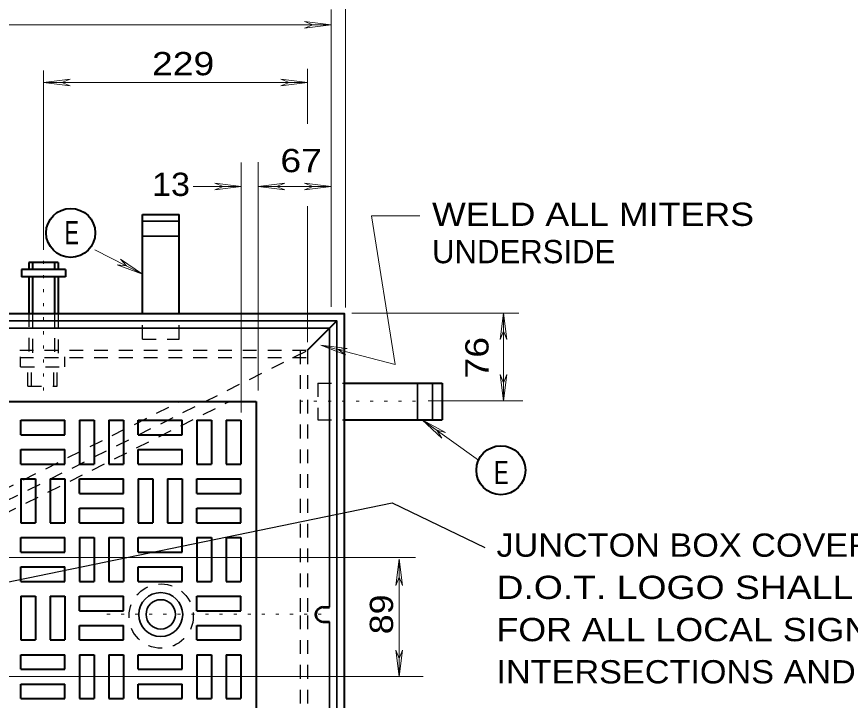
# Model space of a CAD drawing. Extents: x 312583 to 312854, y 144419 to 144597.
# Drawn here: x 312714.2 to 312741.44, y 144549.93 to 144572.27 of the extents above; entities that cross this region are included whole.
import ezdxf

# ---------------------------------------------------------------- set-up
doc = ezdxf.new("R2010")
doc.units = 0
doc.header["$LTSCALE"] = 0.3
doc.linetypes.add('DOTTED', pattern=[1.5, 0.3, -1.2])
doc.linetypes.add('SHORT_DASHED', pattern=[2.7, 1.5, -1.2])
doc.layers.add('1', color=7, linetype='Continuous', lineweight=40)
doc.layers.add('2', color=7, linetype='Continuous', lineweight=13)

msp = doc.modelspace()

# ---------------------------------------------------------------- linework, layer by layer
at = {"layer": '1'}
for p, q in [((312718.3075, 144565.8076), (312719.5112, 144565.8076)), ((312718.3075, 144562.5876), (312718.3075, 144565.8076)), ((312719.5112, 144562.5799), (312719.5112, 144565.8076)), ((312715.5552, 144564.2436), (312714.5969, 144564.2436)), ((312714.5969, 144564.2436), (312714.5969, 144564.0059)), ((312714.7195, 144564.2436), (312714.7195, 144564.0059)), ((312715.4325, 144564.2436), (312715.4325, 144564.0059)), ((312715.5552, 144564.2436), (312715.5552, 144564.0059)), ((312715.7929, 144564.0059), (312714.3592, 144564.0059)), ((312714.3592, 144564.0059), (312714.3592, 144563.7683)), ((312715.7929, 144564.0059), (312715.7929, 144563.7683)), ((312715.7929, 144563.7683), (312714.3592, 144563.7683)), ((312714.5969, 144563.7683), (312714.5969, 144562.5876)), ((312714.7195, 144563.7683), (312714.7195, 144562.5646)), ((312715.4325, 144563.7683), (312715.4325, 144562.5723)), ((312715.5552, 144563.7683), (312715.5552, 144562.5799)), ((312723.7049, 144561.3686), (312724.6632, 144562.3269)), ((312724.9009, 144560.2953), (312728.1055, 144560.2953)), ((312728.1055, 144560.2953), (312728.1055, 144559.0916)), ((312690.8762, 144559.6973), (312722.0259, 144559.6973)), ((312722.0259, 144559.6973), (312722.0259, 144545.7976)), ((312714.3362, 144559.0839), (312715.7699, 144559.0839)), ((312714.3362, 144558.6086), (312714.3362, 144559.0839)), ((312715.7699, 144558.6086), (312715.7699, 144559.0839)), ((312716.2529, 144559.0839), (312716.2529, 144557.6503)), ((312716.2529, 144559.0839), (312716.7282, 144559.0839)), ((312716.7282, 144559.0839), (312716.7282, 144557.6503)), ((312717.2112, 144559.0839), (312717.2112, 144557.6503)), ((312717.2112, 144559.0839), (312717.6865, 144559.0839)), ((312717.6865, 144559.0839), (312717.6865, 144557.6503)), ((312718.1695, 144559.0839), (312719.6032, 144559.0839)), ((312718.1695, 144558.6086), (312718.1695, 144559.0839)), ((312719.6032, 144558.6086), (312719.6032, 144559.0839)), ((312720.0862, 144559.0839), (312720.0862, 144557.6503)), ((312720.0862, 144559.0839), (312720.5615, 144559.0839)), ((312720.5615, 144559.0839), (312720.5615, 144557.6503)), ((312721.0445, 144559.0839), (312721.0445, 144557.6503)), ((312721.0445, 144559.0839), (312721.5199, 144559.0839)), ((312721.5199, 144559.0839), (312721.5199, 144557.6503)), ((312724.9392, 144559.0916), (312728.1055, 144559.0916)), ((312714.3362, 144558.6086), (312715.7699, 144558.6086)), ((312718.1695, 144558.6086), (312719.6032, 144558.6086)), ((312714.3362, 144558.1256), (312715.7699, 144558.1256)), ((312714.3362, 144557.6503), (312714.3362, 144558.1256)), ((312715.7699, 144557.6503), (312715.7699, 144558.1256)), ((312718.1695, 144558.1256), (312719.6032, 144558.1256)), ((312718.1695, 144557.6503), (312718.1695, 144558.1256)), ((312719.6032, 144557.6503), (312719.6032, 144558.1256)), ((312714.3362, 144557.6503), (312715.7699, 144557.6503)), ((312716.2529, 144557.6503), (312716.7282, 144557.6503)), ((312717.2112, 144557.6503), (312717.6865, 144557.6503)), ((312718.1695, 144557.6503), (312719.6032, 144557.6503)), ((312720.0862, 144557.6503), (312720.5615, 144557.6503)), ((312721.0445, 144557.6503), (312721.5199, 144557.6503)), ((312714.3362, 144557.1673), (312714.3362, 144555.7336)), ((312714.3362, 144557.1673), (312714.8115, 144557.1673)), ((312714.8115, 144557.1673), (312714.8115, 144555.7336)), ((312715.2945, 144557.1673), (312715.2945, 144555.7336)), ((312715.2945, 144557.1673), (312715.7699, 144557.1673)), ((312715.7699, 144557.1673), (312715.7699, 144555.7336)), ((312716.2529, 144557.1673), (312717.6865, 144557.1673)), ((312716.2529, 144556.6919), (312716.2529, 144557.1673)), ((312717.6865, 144556.6919), (312717.6865, 144557.1673)), ((312718.1695, 144557.1673), (312718.1695, 144555.7336)), ((312718.1695, 144557.1673), (312718.6449, 144557.1673)), ((312718.6449, 144557.1673), (312718.6449, 144555.7336)), ((312719.1279, 144557.1673), (312719.1279, 144555.7336)), ((312719.1279, 144557.1673), (312719.6032, 144557.1673)), ((312719.6032, 144557.1673), (312719.6032, 144555.7336)), ((312720.0862, 144557.1673), (312721.5199, 144557.1673)), ((312720.0862, 144556.6919), (312720.0862, 144557.1673)), ((312721.5199, 144556.6919), (312721.5199, 144557.1673)), ((312716.2529, 144556.6919), (312717.6865, 144556.6919)), ((312720.0862, 144556.6919), (312721.5199, 144556.6919)), ((312716.2529, 144556.2089), (312717.6865, 144556.2089)), ((312716.2529, 144555.7336), (312716.2529, 144556.2089)), ((312717.6865, 144555.7336), (312717.6865, 144556.2089)), ((312720.0862, 144556.2089), (312721.5199, 144556.2089)), ((312720.0862, 144555.7336), (312720.0862, 144556.2089)), ((312721.5199, 144555.7336), (312721.5199, 144556.2089)), ((312714.3362, 144555.7336), (312714.8115, 144555.7336)), ((312715.2945, 144555.7336), (312715.7699, 144555.7336)), ((312716.2529, 144555.7336), (312717.6865, 144555.7336)), ((312718.1695, 144555.7336), (312718.6449, 144555.7336)), ((312719.1279, 144555.7336), (312719.6032, 144555.7336)), ((312720.0862, 144555.7336), (312721.5199, 144555.7336)), ((312714.3362, 144555.2506), (312715.7699, 144555.2506)), ((312714.3362, 144554.7753), (312714.3362, 144555.2506)), ((312715.7699, 144554.7753), (312715.7699, 144555.2506)), ((312716.2529, 144555.2506), (312716.2529, 144553.8169)), ((312716.2529, 144555.2506), (312716.7282, 144555.2506)), ((312716.7282, 144555.2506), (312716.7282, 144553.8169)), ((312717.2112, 144555.2506), (312717.2112, 144553.8169)), ((312717.2112, 144555.2506), (312717.6865, 144555.2506)), ((312717.6865, 144555.2506), (312717.6865, 144553.8169)), ((312718.1695, 144555.2506), (312719.6032, 144555.2506)), ((312718.1695, 144554.7753), (312718.1695, 144555.2506)), ((312719.6032, 144554.7753), (312719.6032, 144555.2506)), ((312720.0862, 144555.2506), (312720.0862, 144553.8169)), ((312720.0862, 144555.2506), (312720.5615, 144555.2506)), ((312720.5615, 144555.2506), (312720.5615, 144553.8169)), ((312721.0445, 144555.2506), (312721.0445, 144553.8169)), ((312721.0445, 144555.2506), (312721.5199, 144555.2506)), ((312721.5199, 144555.2506), (312721.5199, 144553.8169)), ((312714.3362, 144554.7753), (312715.7699, 144554.7753)), ((312718.1695, 144554.7753), (312719.6032, 144554.7753)), ((312714.3362, 144554.2923), (312715.7699, 144554.2923)), ((312714.3362, 144553.8169), (312714.3362, 144554.2923)), ((312715.7699, 144553.8169), (312715.7699, 144554.2923)), ((312718.1695, 144554.2923), (312719.6032, 144554.2923)), ((312718.1695, 144553.8169), (312718.1695, 144554.2923)), ((312719.6032, 144553.8169), (312719.6032, 144554.2923)), ((312714.3362, 144553.8169), (312715.7699, 144553.8169)), ((312716.2529, 144553.8169), (312716.7282, 144553.8169)), ((312717.2112, 144553.8169), (312717.6865, 144553.8169)), ((312718.1695, 144553.8169), (312719.6032, 144553.8169)), ((312720.0862, 144553.8169), (312720.5615, 144553.8169)), ((312721.0445, 144553.8169), (312721.5199, 144553.8169)), ((312714.3362, 144553.3339), (312714.3362, 144551.9003)), ((312714.3362, 144553.3339), (312714.8115, 144553.3339)), ((312714.8115, 144553.3339), (312714.8115, 144551.9003)), ((312715.2945, 144553.3339), (312715.2945, 144551.9003)), ((312715.2945, 144553.3339), (312715.7699, 144553.3339)), ((312715.7699, 144553.3339), (312715.7699, 144551.9003)), ((312716.2529, 144553.3339), (312717.6865, 144553.3339)), ((312716.2529, 144552.8586), (312716.2529, 144553.3339)), ((312717.6865, 144552.8586), (312717.6865, 144553.3339)), ((312720.0862, 144553.3339), (312721.5199, 144553.3339)), ((312720.0862, 144552.8586), (312720.0862, 144553.3339)), ((312721.5199, 144552.8586), (312721.5199, 144553.3339)), ((312716.2529, 144552.8586), (312717.6865, 144552.8586)), ((312720.0862, 144552.8586), (312721.5199, 144552.8586)), ((312716.2529, 144552.3756), (312717.6865, 144552.3756)), ((312716.2529, 144551.9003), (312716.2529, 144552.3756)), ((312717.6865, 144551.9003), (312717.6865, 144552.3756)), ((312720.0862, 144552.3756), (312721.5199, 144552.3756)), ((312720.0862, 144551.9003), (312720.0862, 144552.3756)), ((312721.5199, 144551.9003), (312721.5199, 144552.3756)), ((312714.3362, 144551.9003), (312714.8115, 144551.9003)), ((312715.2945, 144551.9003), (312715.7699, 144551.9003)), ((312716.2529, 144551.9003), (312717.6865, 144551.9003)), ((312720.0862, 144551.9003), (312721.5199, 144551.9003)), ((312714.3362, 144551.4173), (312715.7699, 144551.4173)), ((312714.3362, 144550.9419), (312714.3362, 144551.4173)), ((312715.7699, 144550.9419), (312715.7699, 144551.4173)), ((312716.2529, 144551.4173), (312716.2529, 144549.9836)), ((312716.2529, 144551.4173), (312716.7282, 144551.4173)), ((312716.7282, 144551.4173), (312716.7282, 144549.9836)), ((312717.2112, 144551.4173), (312717.2112, 144549.9836)), ((312717.2112, 144551.4173), (312717.6865, 144551.4173)), ((312717.6865, 144551.4173), (312717.6865, 144549.9836)), ((312718.1695, 144551.4173), (312719.6032, 144551.4173)), ((312718.1695, 144550.9419), (312718.1695, 144551.4173)), ((312719.6032, 144550.9419), (312719.6032, 144551.4173)), ((312720.0862, 144551.4173), (312720.0862, 144549.9836)), ((312720.0862, 144551.4173), (312720.5615, 144551.4173)), ((312720.5615, 144551.4173), (312720.5615, 144549.9836)), ((312721.0445, 144551.4173), (312721.0445, 144549.9836)), ((312721.0445, 144551.4173), (312721.5199, 144551.4173)), ((312721.5199, 144551.4173), (312721.5199, 144549.9836)), ((312714.3362, 144550.9419), (312715.7699, 144550.9419)), ((312718.1695, 144550.9419), (312719.6032, 144550.9419)), ((312714.3362, 144550.4589), (312715.7699, 144550.4589)), ((312714.3362, 144549.9836), (312714.3362, 144550.4589)), ((312715.7699, 144549.9836), (312715.7699, 144550.4589)), ((312718.1695, 144550.4589), (312719.6032, 144550.4589)), ((312718.1695, 144549.9836), (312718.1695, 144550.4589)), ((312719.6032, 144549.9836), (312719.6032, 144550.4589)), ((312714.3362, 144549.9836), (312715.7699, 144549.9836)), ((312716.2529, 144549.9836), (312716.7282, 144549.9836)), ((312717.2112, 144549.9836), (312717.6865, 144549.9836)), ((312718.1695, 144549.9836), (312719.6032, 144549.9836)), ((312720.0862, 144549.9836), (312720.5615, 144549.9836)), ((312721.0445, 144549.9836), (312721.5199, 144549.9836))]:
    msp.add_line(p, q, dxfattribs=at)
at = {"layer": '1', "lineweight": 35}
for p, q in [((312718.3075, 144565.5853), (312719.5112, 144565.5853)), ((312718.3075, 144565.1023), (312719.5112, 144565.1023)), ((312688.4842, 144562.0893), (312724.4179, 144562.0893)), ((312724.4179, 144562.0893), (312724.4179, 144552.9736)), ((312727.3005, 144560.2953), (312727.3005, 144559.0916)), ((312727.7835, 144560.2953), (312727.7835, 144559.0916)), ((312724.4179, 144552.4906), (312724.4179, 144543.4056))]:
    msp.add_line(p, q, dxfattribs=at)
at = {"layer": '1', "linetype": 'DOTTED', "lineweight": 13}
for p, q in [((312715.0799, 144564.7496), (312715.0799, 144559.9273)), ((312723.4519, 144559.7049), (312727.3312, 144559.7049)), ((312717.1499, 144552.7436), (312724.3489, 144552.7436))]:
    msp.add_line(p, q, dxfattribs=at)
at = {"layer": '1', "linetype": 'SHORT_DASHED', "lineweight": 25}
for p, q in [((312714.5969, 144562.5876), (312714.5969, 144561.1309)), ((312714.7195, 144562.5493), (312714.7195, 144561.1309)), ((312715.4325, 144562.5799), (312715.4325, 144561.1309)), ((312715.5552, 144562.5339), (312715.5552, 144561.1309)), ((312718.3075, 144561.7366), (312718.3075, 144562.5876)), ((312719.5112, 144561.7366), (312719.5112, 144562.5799)), ((312718.3075, 144561.7366), (312719.5112, 144561.7366)), ((312689.2049, 144544.1186), (312723.7049, 144561.3686)), ((312723.4595, 144561.3686), (312723.4595, 144552.7053)), ((312698.9109, 144561.1309), (312723.7049, 144561.1309)), ((312714.3285, 144560.8319), (312714.3285, 144561.1539)), ((312715.7699, 144560.8319), (312715.7699, 144561.1539)), ((312714.3285, 144560.8319), (312715.7699, 144560.8319)), ((312714.5662, 144560.1956), (312714.5662, 144560.8319)), ((312714.6889, 144560.1956), (312714.6889, 144560.8319)), ((312715.4095, 144560.1956), (312715.4095, 144560.8319)), ((312715.5245, 144560.1956), (312715.5245, 144560.8319)), ((312714.5662, 144560.1956), (312715.5245, 144560.1956)), ((312724.0345, 144560.2953), (312724.0345, 144559.0916)), ((312724.0345, 144560.2953), (312724.8855, 144560.2953)), ((312706.4549, 144553.1499), (312719.5419, 144559.6973)), ((312707.2522, 144552.7436), (312721.1519, 144559.6973)), ((312724.0345, 144559.0916), (312724.9239, 144559.0916)), ((312723.4595, 144552.7053), (312723.4595, 144544.1186))]:
    msp.add_line(p, q, dxfattribs=at)
at = {"layer": '1', "lineweight": 53}
for p, q in [((312724.2109, 144552.9736), (312724.4179, 144552.9736)), ((312724.2109, 144552.4906), (312724.4179, 144552.4906))]:
    msp.add_line(p, q, dxfattribs=at)
at = {"layer": '1'}
msp.add_lwpolyline([(312688.0012, 144562.5723), (312724.9009, 144562.5723), (312724.9009, 144542.9226)], dxfattribs=at)
at = {"layer": '1', "lineweight": 35}
msp.add_lwpolyline([(312688.2465, 144562.3269), (312724.6632, 144562.3269), (312724.6632, 144543.1603)], dxfattribs=at)
at = {"layer": '1', "linetype": 'SHORT_DASHED', "lineweight": 25}
for points in [[(312689.2049, 144561.3686), (312698.9109, 144561.3686), (312723.7049, 144561.3686)], [(312723.7049, 144561.3686), (312723.7049, 144552.7053), (312723.7049, 144544.1186)]]:
    msp.add_lwpolyline(points, dxfattribs=at)
at = {"layer": '1', "lineweight": 25}
msp.add_lwpolyline([(312711.6529, 144553.3339), (312726.4725, 144556.3853), (312729.4932, 144554.9286)], dxfattribs=at)
at = {"layer": '1', "linetype": 'SHORT_DASHED', "lineweight": 25}
msp.add_circle((312718.9213, 144552.6823), 1.0502, dxfattribs=at)
at = {"layer": '1', "lineweight": 35}
for centre, radius in [((312718.9048, 144552.7317), 0.7188), ((312718.9074, 144552.7379), 0.4792)]:
    msp.add_circle(centre, radius, dxfattribs=at)
at = {"layer": '1', "lineweight": 53}
msp.add_arc((312724.207, 144552.7331), 0.2396, 90, 270, dxfattribs=at)
at = {"layer": '2'}
for p, q in [((312724.9392, 144562.7639), (312724.9392, 144574.9386)), ((312724.4715, 144562.7946), (312724.4715, 144572.5083)), ((312688.4535, 144572.0099), (312724.4715, 144572.0099)), ((312723.6052, 144572.1173), (312723.8812, 144572.0099)), ((312724.4715, 144572.0099), (312723.6052, 144572.1173)), ((312723.6052, 144571.9026), (312723.8812, 144572.0099)), ((312724.4715, 144572.0099), (312723.6052, 144571.9026)), ((312715.0799, 144564.7496), (312715.0799, 144570.5149)), ((312723.6972, 144568.7669), (312723.6972, 144570.5686)), ((312715.0799, 144570.1239), (312715.9462, 144570.2313)), ((312715.9462, 144570.2313), (312715.6702, 144570.1239)), ((312722.8309, 144570.2313), (312723.1069, 144570.1239)), ((312723.6972, 144570.1239), (312722.8309, 144570.2313)), ((312715.0799, 144570.1239), (312723.6972, 144570.1239)), ((312715.0799, 144570.1239), (312715.9462, 144570.0166)), ((312715.9462, 144570.0166), (312715.6702, 144570.1239)), ((312722.8309, 144570.0166), (312723.1069, 144570.1239)), ((312723.6972, 144570.1239), (312722.8309, 144570.0166)), ((312721.5352, 144559.3369), (312721.5352, 144567.5096)), ((312722.0949, 144560.0499), (312722.0949, 144567.5173)), ((312721.5352, 144566.7199), (312719.9635, 144566.7199)), ((312720.6689, 144566.8273), (312720.9449, 144566.7199)), ((312721.5352, 144566.7199), (312720.6689, 144566.8273)), ((312720.6689, 144566.6126), (312720.9449, 144566.7199)), ((312721.5352, 144566.7199), (312720.6689, 144566.6126)), ((312722.0949, 144566.7199), (312722.9612, 144566.8273)), ((312722.0949, 144566.7199), (312724.4715, 144566.7199)), ((312722.0949, 144566.7199), (312722.9612, 144566.6126)), ((312722.9612, 144566.8273), (312722.6852, 144566.7199)), ((312722.9612, 144566.6126), (312722.6852, 144566.7199)), ((312723.6052, 144566.8273), (312723.8812, 144566.7199)), ((312724.4715, 144566.7199), (312723.6052, 144566.8273)), ((312723.6052, 144566.6126), (312723.8812, 144566.7199)), ((312724.4715, 144566.7199), (312723.6052, 144566.6126)), ((312723.6972, 144561.6293), (312723.6972, 144566.0836)), ((312725.7902, 144565.7693), (312727.3695, 144565.7693)), ((312716.7512, 144564.6576), (312718.3075, 144563.8603)), ((312717.5869, 144564.3509), (312717.7862, 144564.1286)), ((312718.3075, 144563.8603), (312717.5869, 144564.3509)), ((312717.4872, 144564.1593), (312717.7862, 144564.1286)), ((312718.3075, 144563.8603), (312717.4872, 144564.1593)), ((312725.1539, 144562.5876), (312730.6049, 144562.5876)), ((312730.1065, 144562.5876), (312729.9992, 144561.7213)), ((312730.1065, 144562.5876), (312730.1065, 144559.7126)), ((312730.1065, 144562.5876), (312730.2139, 144561.7213)), ((312729.9992, 144561.7213), (312730.1065, 144561.9973)), ((312730.2139, 144561.7213), (312730.1065, 144561.9973)), ((312724.1342, 144561.5373), (312724.9469, 144561.2153)), ((312724.1342, 144561.5373), (312725.0005, 144561.4223)), ((312725.0005, 144561.4223), (312724.7092, 144561.3916)), ((312724.9469, 144561.2153), (312724.7092, 144561.3916)), ((312729.9992, 144560.5789), (312730.1065, 144560.3029)), ((312730.1065, 144559.7126), (312729.9992, 144560.5789)), ((312730.2139, 144560.5789), (312730.1065, 144560.3029)), ((312730.1065, 144559.7126), (312730.2139, 144560.5789)), ((312727.6455, 144559.7126), (312730.7429, 144559.7126)), ((312729.2939, 144557.7806), (312727.4462, 144559.0916)), ((312727.4462, 144559.0916), (312728.0902, 144558.5013)), ((312727.4462, 144559.0916), (312728.2129, 144558.6776)), ((312728.0902, 144558.5013), (312727.9292, 144558.7543)), ((312728.2129, 144558.6776), (312727.9292, 144558.7543)), ((312712.2509, 144554.5989), (312727.2319, 144554.5989)), ((312726.6944, 144554.5453), (312726.5871, 144553.6789)), ((312726.6944, 144554.5453), (312726.6944, 144550.7043)), ((312726.6944, 144554.5453), (312726.8018, 144553.6789)), ((312726.5871, 144553.6789), (312726.6944, 144553.9549)), ((312726.8018, 144553.6789), (312726.6944, 144553.9549)), ((312726.5871, 144551.5706), (312726.6944, 144551.2946)), ((312726.6944, 144550.7043), (312726.5871, 144551.5706)), ((312726.8018, 144551.5706), (312726.6944, 144551.2946)), ((312726.6944, 144550.7043), (312726.8018, 144551.5706)), ((312712.3352, 144550.7043), (312727.4799, 144550.7043))]:
    msp.add_line(p, q, dxfattribs=at)
msp.add_lwpolyline([(312725.7902, 144565.7693), (312726.5645, 144560.9009), (312724.1342, 144561.5373)], dxfattribs=at)
at = {"layer": '2', "lineweight": 40}
for centre in [(312715.9644, 144565.2048), (312730.0212, 144557.4481)]:
    msp.add_circle(centre, 0.8012, dxfattribs=at)

# ---------------------------------------------------------------- texts
at = {"layer": '1'}
for s, width, p in [('JUNCTON BOX COVER WTHOUT', 1.1, (312729.8765, 144554.6209)), ('D.O.T. LOGO SHALL BE UTILIZED', 1.2, (312729.8765, 144553.2409)), ('FOR ALL LOCAL SIGNALIZED', 1.15, (312729.8765, 144551.8609)), ('INTERSECTIONS AND BRIDGES', 1.1, (312729.8765, 144550.4809))]:
    msp.add_text(s, height=0.76, dxfattribs=dict(at, width=width)).set_placement(p)
at = {"layer": '2'}
for s, width, p in [('229 ', 1.2, (312718.6208, 144570.3587)), ('67 ', 1.2, (312722.817, 144567.1903)), ('13 ', 1.1, (312718.6202, 144566.4142)), ('WELD ALL MITERS', 1.15, (312727.772, 144565.4348)), ('E', 0.7, (312715.7594, 144564.831)), ('E', 0.7, (312729.797, 144556.9948))]:
    msp.add_text(s, height=0.76, dxfattribs=dict(at, width=width)).set_placement(p)
msp.add_text('UNDERSIDE', height=0.76, dxfattribs=at).set_placement((312727.772, 144564.2148))
for s, width, p in [('76 ', 1.2, (312729.6176, 144560.4473)), ('89 ', 1.15, (312726.4969, 144552.0882))]:
    msp.add_text(s, height=0.76, rotation=90, dxfattribs=dict(at, width=width)).set_placement(p)

doc.saveas('drawing.dxf')
